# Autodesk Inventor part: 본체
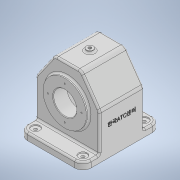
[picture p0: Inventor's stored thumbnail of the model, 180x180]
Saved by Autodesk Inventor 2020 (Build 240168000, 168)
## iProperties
Created: 2022-12
Part Number: 본체
Material: 일반
Document SubType Name: Modeling
Designer: 1강의실14
Density: 1 g/cm^3
Appearance: 기본값
Mass: 347.033 g
Surface Area: 1065.53 cm^2
Volume: 347.033 cm^3
Author: 1강의실14
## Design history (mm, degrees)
sketch "스케치1"
  geometry: L1 (-55, 67)-(55, 67); L2 (55, 67)-(55, -67); L3 (55, -67)-(-55, -67); L4 (-55, -67)-(-55, 67); L5 (-55, 67)-(55, -67); L6 (55, 67)-(-55, -67); 1 further point
  constraints: 12 end point, 2 midpoint, 2 parallel, 1 horizontal, 1 perpendicular
  dimensions: "d0" = 110 distance of L2.end L3.end; "d1" = 134 distance of L1.end L2.end
extrude "돌출1" new body sketch "스케치1" distance "d2" = 12; taper "d3" = 0 deg
sketch "스케치2"
  geometry: L1 (-55, 12)-(55, 12) reference; L2 (55, 12)-(-55, 12) reference; L3 (-55, 0)-(55, 0) reference; L4 (23.491, 122)-(55, 77); L5 (55, 77)-(55, 12); L6 (-55, 77)-(-55, 12); L7 (23.491, 122)-(-23.491, 122); L8 (-23.491, 122)-(-55, 77); 2 further points
  constraints: 10 end point, 2 perpendicular, 1 horizontal, 1 horizontal alignment, 1 midpoint
  dimensions: "d8" = 35 deg angle of L4 L5; "d9" = 65 distance of L1.start L6.start; "d10" = 35 deg angle of L6 L8; "d38" = 122 distance between parallel lines of L3 L7
extrude "돌출2" join sketch "스케치2" stored distance "d11" = 77; taper "d12" = 0 deg
fillet "모깎기1" dims "d13" = 14
sketch "스케치3"
  geometry: A1 r 14 centre (-41, -53) between (-55, -53) and (-41, -67) reference; A2 r 14 centre (41, -53) between (41, -67) and (55, -53) reference; A3 r 14 centre (41, 53) between (55, 53) and (41, 67) reference; A4 r 14 centre (-41, 53) between (-41, 67) and (-55, 53) reference; 5 further points
  constraints: 4 coincident
hole "구멍1" sketch "스케치3" at (-41, -53), (41, -53), (41, 53), (-41, 53) diameter "d14" = 5.5; stored, may be unused: countersink angle "d18" = 90 deg, drill point angle "d20" = 118 deg; dims "d15" = 11, "d16" = 15, "d17" = 2, "d19" = 14
sketch "스케치5"
  geometry: L1 (-41, 0)-(41, 0) reference; C1 r 37.5 at (0, 65); 2 further points
  constraints: 1 centre point, 1 midpoint, 1 vertical alignment
  dimensions: "d21" = 37.5 radius of C1; "d22" = 65 distance from line of C1.centre L1
extrude "돌출3" join sketch "스케치5" distance "d23" = 5; taper "d24" = 0 deg
sketch "스케치6"
  geometry: L1 (-41, 0)-(41, 0) reference; C1 r 31 at (0, 65); 2 further points
  constraints: 1 centre point, 1 midpoint, 1 vertical alignment
  dimensions: "d25" = 31 radius of C1; "d26" = 65 distance from line of L1 C1.centre
extrude "돌출4" join sketch "스케치6" distance "d27" = 10; taper "d28" = 0 deg
sketch "스케치7"
  geometry: L1 (102.5, 43.5)-(27.5, 43.5) reference; L2 (102.5, 38.5)-(102.5, 43.5) reference; L3 (34, -48.5)-(96, -48.5) reference; L4 (96, -38.5)-(96, -48.5) reference; L5 (65, 43.5)-(65, -48.5); L6 (0, -53)-(0, 53) reference; L7 (85, 43.5)-(85, 19.5); L8 (85, -33.5)-(85, -48.5); L9 (122, -38.5)-(122, 38.5) reference; L10 (77, -38.5)-(122, -38.5) reference; L11 (122, 38.5)-(77, 38.5) reference; L12 (85, -33.5)-(85, 19.5); 1 further point
  constraints: 8 end point, 2 midpoint, 2 point on line, 1 perpendicular, 1 vertical
  dimensions: "d29" = 65 distance between parallel lines of L6 L5; "d30" = 24 distance of L7.start L7.end; "d31" = 15 distance of L8.start L8.end; "d34" = 40 diameter of L7 L5; "d36" = 40 diameter of L8 L5
revolve "회전1" sketch "스케치7" stored, may be unused: angle "d41" = 90 deg
node "작업 평면1"
sketch "스케치8"
  geometry: L1 (-55, 12)-(55, 12) reference; L2 (-55, 12)-(-55, 77) reference; L3 (-55, 77)-(-23.491, 122) reference; L4 (-23.491, 122)-(23.491, 122) reference; L5 (23.491, 122)-(55, 77) reference; L6 (55, 77)-(55, 12) reference; L7 (20.888, 117)-(-20.888, 117); L8 (-20.888, 117)-(-50, 75.424); L9 (-50, 75.424)-(-50, 17); L10 (-50, 17)-(50, 17); L11 (50, 17)-(50, 75.424); L12 (50, 75.424)-(20.888, 117); L13 (41, 0)-(-41, 0) reference; L14 (55, 0)-(41, 0) reference; L15 (-41, 0)-(-55, 0) reference; L16 (-50, 17)-(-50, 0); L17 (50, 17)-(50, 0); C1 r 37.5 at (0, 65) reference; 1 further point
  constraints: 16 end point, 2 point on line, 1 parallel, 1 vertical, 5 other
  dimensions: "d43" = 5 distance between parallel lines of L4 L7
extrude "돌출5" cut sketch "스케치8" distance "d44" = 67; taper "d45" = 0 deg
sketch "스케치9"
  geometry: L1 (65, 33.5)-(65, -33.5); L2 (0, -33.5)-(0, 33.5) reference; L3 (45, 33.5)-(85, 33.5) reference; L4 (146.4, -33.5)-(-24.4, -33.5) reference; L5 (65, 19.5)-(38, 19.5); L6 (38, 19.5)-(24, 33.5); L7 (75.424, 33.5)-(0, 33.5) reference; L8 (45, 43.5)-(85, 43.5) reference; 1 further point
  constraints: 6 end point, 3 point on line, 1 perpendicular, 1 vertical
  dimensions: "d46" = 65 distance between parallel lines of L2 L1; "d47" = 135 deg angle of L7 L6; "d48" = 24 distance between parallel lines of L8 L5; "d49" = 54 diameter of L5.end L1
revolve "회전2" sketch "스케치9" stored, may be unused: angle "d50" = 90 deg
sketch "스케치10"
  geometry: C1 r 20 at (0, 0) reference; 1 further point
extrude "돌출6" cut sketch "스케치10" distance "d51" = 67; taper "d52" = 0 deg
chamfer "모따기1" distance "d53" = 1; stored, may be unused: second distance "d54" = 2, angle "d55" = 45 deg
chamfer "모따기2" distance "d56" = 1; stored, may be unused: second distance "d57" = 2, angle "d58" = 45 deg
node "작업 평면2"
sketch "스케치12"
  geometry: L1 (-55, -38.5)-(-55, 38.5) reference; L2 (23.491, 38.5)-(-23.491, 38.5) reference; C1 r 6 at (0, 0); 1 further point
  constraints: 1 centre point
  dimensions: "d62" = 6 radius of C1; "d63" = 55 distance from line of L1 C1.centre; "d64" = 38.5 distance from line of L2 C1.centre
extrude "돌출7" join sketch "스케치12" stored distance "d65" = 67; taper "d66" = 0 deg
sketch "스케치13"
  geometry: C1 r 6 at (0, 0) reference; 2 further points
  constraints: 1 coincident
hole "구멍2" sketch "스케치13" at (0, 0) diameter "d67" = 5.1881; stored, may be unused: countersink angle "d71" = 90 deg, drill point angle "d73" = 118 deg; dims "d68" = 12, "d69" = 15, "d70" = 2, "d72" = 16
fillet "모깎기2" dims "d74" = 3
fillet "모깎기3" dims "d75" = 10
sketch "스케치15" dims "d77" = 29
  geometry: L1 (0, 0)-(0, 29); C1 r 37.5 at (0, 0) reference; 2 further points
  constraints: 2 coincident, 2 end point, 1 vertical, 1 vertical alignment, 2 other
hole "구멍3" sketch "스케치15" at (0, 29) diameter "d78" = 2.459; stored, may be unused: countersink angle "d82" = 90 deg, drill point angle "d84" = 118 deg; dims "d79" = 6, "d80" = 15, "d81" = 2, "d83" = 8
sketch "스케치16" dims "d88" = 26
  geometry: L1 (0, 0)-(0, 26); C1 r 31 at (0, 0) reference; 2 further points
  constraints: 2 coincident, 2 end point, 1 vertical, 1 vertical alignment, 2 other
hole "구멍4" sketch "스케치16" at (0, 26) diameter "d89" = 2.459; stored, may be unused: countersink angle "d93" = 90 deg, drill point angle "d95" = 118 deg; dims "d90" = 6, "d91" = 15, "d92" = 2, "d94" = 8
fillet "모깎기4" dims "d99" = 3
fillet "모깎기5" dims "d100" = 3
fillet "모깎기6" dims "d101" = 3
fillet "모깎기7" dims "d105" = 3
fillet "모깎기8" dims "d106" = 3
sketch "스케치17"
  geometry: L1 (0, 0)-(106, 0) reference; L2 (14.5, 73.847)-(14.5, 15) reference; 2 further points
  constraints: 1 other
  dimensions: "d107" = 50 distance from line of L1 point (53, 50); "d108" = 38.5 distance from line of L2 point (53, 50)
feature "엠보싱1" sketch "스케치17" dims "d0" = 110, "d1" = 134, "d109" = 0.5, "d110" = 0
fillet "모깎기9" dims "d111" = 3
node "솔리드1"
pattern_circular "원형 패턴1" dims angle "d86" = 360 deg
pattern_circular "원형 패턴2" dims angle "d97" = 360 deg
node "투영된 루프1"
node "투영된 루프2"
feature "A9D066F2-1C7D-4E18-AEED-F7BC21143FA4" dims "d14" = 5.5, "d15" = 11, "d16" = 15, "d17" = 2, "d18" = 90 deg, "d19" = 14, "d20" = 118 deg
other parameters: "d42" = -5, "d61" = -126
